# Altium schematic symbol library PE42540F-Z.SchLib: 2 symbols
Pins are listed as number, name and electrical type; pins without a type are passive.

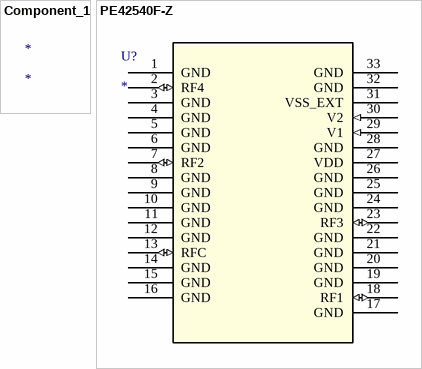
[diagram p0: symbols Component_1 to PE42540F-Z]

## Component_1
designator *

## PE42540F-Z
designator U?
No Description Available; Mfr_Name: Peregine Semiconductor
footprint PE42540F-Z_PSE
footprint PE42540F-Z_PSE
pins: 1 GND (power), 2 RF4 (io), 3 GND (power), 4 GND (power), 5 GND (power), 6 GND (power), 7 RF2 (io), 8 GND (power), 9 GND (power), 10 GND (power), 11 GND (power), 12 GND (power), 13 RFC (io), 14 GND (power), 15 GND (power), 16 GND (power), 17 GND (power), 18 RF1 (io), 19 GND (power), 20 GND (power), 21 GND (power), 22 GND (power), 23 RF3 (io), 24 GND (power), 25 GND (power), 26 GND (power), 27 VDD (power), 28 GND (power), 29 V1 (in), 30 V2 (in), 31 VSS_EXT (power), 32 GND (power), 33 GND (power)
